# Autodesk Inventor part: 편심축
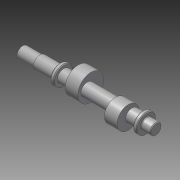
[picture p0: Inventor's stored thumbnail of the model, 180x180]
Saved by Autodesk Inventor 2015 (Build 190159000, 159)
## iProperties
Created: 2021-06
Part Number: 편심축
Material: 강철, 연강
Document SubType Name: Modeling
Designer: mdu-edu
Density: 7.86 g/cm^3
Appearance: 강철
Author: mdu-edu
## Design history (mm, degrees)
sketch "스케치1"
  geometry: L1 (0, 0)-(180, 0); L2 (180, 0)-(180, -7.5); L3 (180, -7.5)-(167, -7.5); L4 (167, -7.5)-(167, -13); L5 (167, -13)-(162, -13); L6 (162, -13)-(162, -8.5); L7 (162, -8.5)-(56, -8.5); L8 (56, -8.5)-(56, -13); L9 (56, -13)-(51, -13); L10 (51, -13)-(51, -8.5); L11 (51, -8.5)-(24, -8.5); L12 (24, -8.5)-(24, -7.5); L13 (24, -7.5)-(0, -7.5); L14 (0, -7.5)-(0, 0)
  constraints: 28 end point, 6 parallel, 3 horizontal, 3 vertical, 1 collinear, 1 perpendicular
  dimensions: "d0" = 15 diameter of L13 L1; "d2" = 26 diameter of L9 L1; "d3" = 26 diameter of L5 L1; "d4" = 15 diameter of L3 L1; "d5" = 17 diameter of L7 L1; "d6" = 17 diameter of L11 L1; "d7" = 24 distance between parallel lines of L12 L14; "d8" = 51 distance between parallel lines of L14 L10; "d10" = 5 distance of L8.end L9.end; "d11" = 5 distance of L4.end L5.end; "d12" = 13 distance between parallel lines of L4 L2; "d13" = 180 distance between parallel lines of L14 L2
revolve "회전1" sketch "스케치1" stored, may be unused: angle "d14" = 90 deg
node "작업 평면1"
sketch "스케치2"
  geometry: C1 r 17.5 at (0, 5); 1 further point
  constraints: 1 centre point, 1 vertical alignment
  dimensions: "d16" = 35 diameter of C1; "d17" = 5 distance of C1.centre point (0, 0)
extrude "돌출1" join sketch "스케치2" distance "d18" = 17; taper "d19" = 0 deg
node "작업 평면2"
sketch "스케치3"
  geometry: C1 r 15 at (0, -5); 1 further point
  constraints: 1 centre point, 1 vertical alignment
  dimensions: "d21" = 30 diameter of C1; "d22" = 5 distance of point (0, 0) C1.centre
extrude "돌출2" join sketch "스케치3" distance "d23" = 17; taper "d24" = 0 deg
chamfer "모따기1" distance "d29" = 1; stored, may be unused: second distance "d30" = 2, angle "d31" = 45 deg
node "작업 평면3"
sketch "스케치4"
  geometry: L1 (-5.5, 2.5)-(12, 2.5); L2 (12, 2.5)-(12, -2.5); L3 (12, -2.5)-(-5.5, -2.5); L4 (12, 6.5)-(12, -6.5) reference; A1 r 2.5 centre (-5.5, 0) between (-5.5, 2.5) and (-5.5, -2.5); 1 further point
  constraints: 6 end point, 2 point on circle, 2 tangent, 1 centre point, 1 collinear, 1 horizontal, 1 horizontal alignment, 1 midpoint, 1 parallel, 1 perpendicular
  dimensions: "d25" = 5 diameter of A1; "d32" = 20 dimension on A1 L4
extrude "돌출3" cut sketch "스케치4" distance "d27" = 3; taper "d28" = 0 deg
fillet "모깎기1" dims "d33" = 0.6
fillet "모깎기2" dims "d34" = 1
node "솔리드1"
other parameters: "d15" = -70.5, "d20" = -32.5
